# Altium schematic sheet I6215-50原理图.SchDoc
size A4
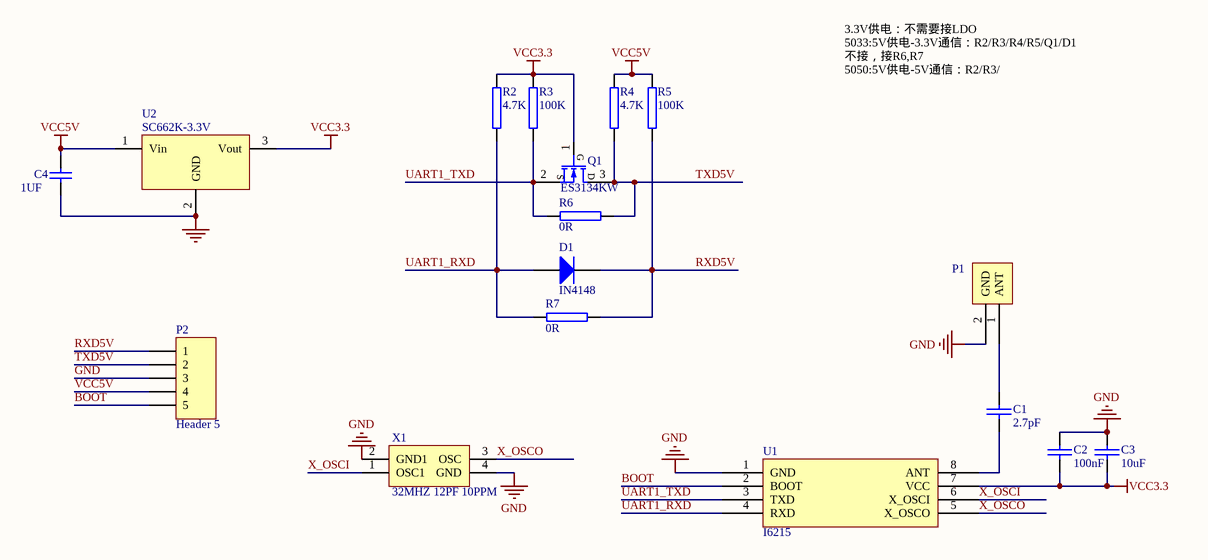
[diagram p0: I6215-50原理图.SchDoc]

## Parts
C1  2.7pF  [0402_C]
C2  100nF  [0402_C]
C3  10uF  [0402_C]
C4  1UF  [0402_C]
D1  IN4148  [SOD-523_L1.2-W0.8-LS1.6-RD]
P1  ANT  [ANT-F-1-2.4G-1.0mmFR4-WCH-KC]  (value not drawn)
P2  Header 5  [HDR1X5]
Q1  ES3134KW  [SOT-523-3_L1.6-W0.8-P1.00-LS1.6-BR]
R2  4.7K  [0402_R]
R3  100K  [0402_R]
R4  4.7K  [0402_R]
R5  100K  [0402_R]
R6  0R  [0402_R]
R7  0R  [0402_R]
U1  I6215  [SOP8]
U2  SC662K-3.3V  [AME8800-3.3]
X1  32MHZ 12PF 10PPM  [crystal oscillator 24MHZ]

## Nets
GND: C2.1 C3.1 C4.2 P1.2(GND) P2.3 U1.1(GND) U2.2(GND) X1.2(GND1) X1.4(GND)
VCC3.3: C2.2 C3.2 Q1.1(G) R2.2 R3.2 U1.7(VCC) U2.3(Vout)
VCC5V: C4.1 P2.4 R4.2 R5.2 U2.1(Vin)
BOOT: P2.5 U1.2(BOOT)
RXD5V: D1.2(K) P2.1 R5.1 R7.1
TXD5V: P2.2 Q1.3(D) R4.1 R6.1
UART1_RXD: D1.1(A) R2.1 R7.2 U1.4(RXD)
UART1_TXD: Q1.2(S) R3.1 R6.2 U1.3(TXD)
X_OSCI: U1.6(X_OSCI) X1.1(OSC1)
X_OSCO: U1.5(X_OSCO) X1.3(OSC)
NetC1_1: C1.1 P1.1(ANT)
NetC1_2: C1.2 U1.8(ANT)

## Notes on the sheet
- 3.3V供电：不需要接LDO
  5033:5V供电-3.3V通信：R2/R3/R4/R5/Q1/D1不接，接R6,R7
  5050:5V供电-5V通信：R2/R3/

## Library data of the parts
C1 = CAP: Capacitor
C2 C3 = CAP: Capacitor; Value: 1.2pF
C4 = Cap: Capacitor; Value: 10UF
D1 = Diode: Default Diode
P2 = Header 5: Header, 5-Pin
Q1 = NMOS
R2-R7 = RES
U2 = VOLTREG
X1 = 16MHZ: value: 12MHZ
